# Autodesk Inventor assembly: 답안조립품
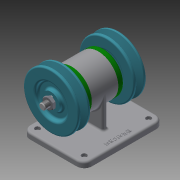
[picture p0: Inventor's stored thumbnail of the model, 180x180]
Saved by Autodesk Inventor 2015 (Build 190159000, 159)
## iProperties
Created: 2019-09
Part Number: 답안조립품
Document SubType Name: Assembly
Designer: now
Author: now
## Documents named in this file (10)
- C:\Users\now\Desktop\490904V1033\답안조립품.iam
- C:\Users\now\Desktop\490904V1033\V-벨트풀리.ipt
- C:\Users\now\Desktop\490904V1033\너트 M10x1.ipt
- C:\Users\now\Desktop\490904V1033\베어링 6004.ipt
- C:\Users\now\Desktop\490904V1033\본체.ipt
- C:\Users\now\Desktop\490904V1033\볼트 M4.ipt
- C:\Users\now\Desktop\490904V1033\오일 실 17 30 5.ipt
- C:\Users\now\Desktop\490904V1033\축.ipt
- C:\Users\now\Desktop\490904V1033\커버.ipt
- C:\Users\now\Desktop\490904V1033\키 5 x 5 x 12.ipt
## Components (2 placed, 1 different names)
1. V-벨트풀리:1 — 각도:4
2. V-벨트풀리:2 — 각도:3
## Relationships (2: Angle 2)
- 각도:3 [Angle]: V-벨트풀리:2
- 각도:4 [Angle]: V-벨트풀리:1
